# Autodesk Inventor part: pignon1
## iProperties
Author: Administrateur
Shininess: 20.0
PropertySet Name: _Private Model Information
Length Units: 11269
Angle Units: 11283
Time Units: 11279
Mass Units: 11290
Length Display Precision: 3
Angle Display Precision: 2
Compacted: False
Created: 2001-04
Part Number: pignon1
Material: Par défaut
Document SubType Name: Modélisation
Designer: Administrateur
Control State: 0
Master: False
Checked Out: False
PropertySet Name: Design Tracking Control
Density: 0.0
Volumn: 0.0
Area: 0.0
PropertySet Name: Model Information
